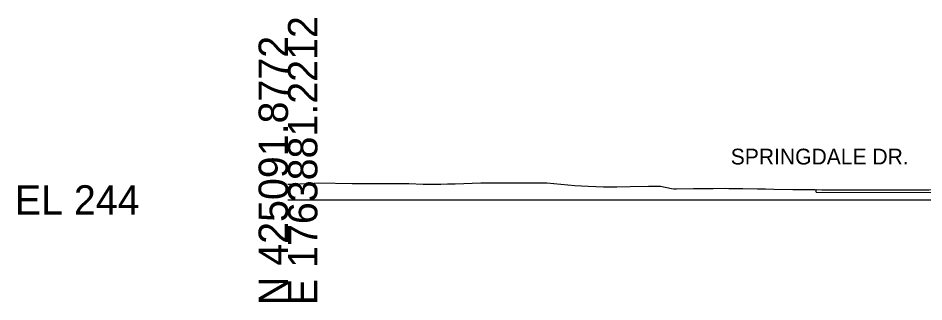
# Model space of a CAD drawing. Extents: x -26 to 3203, y -11010 to 4024.
# Drawn here: x 2974.3 to 3060.5, y -3509.7 to -3482.7 of the extents above; entities that cross this region are included whole.
import ezdxf

# ---------------------------------------------------------------- set-up
doc = ezdxf.new("R2010")
doc.units = 0
for name, color, linetype in [('Default', 7, 'Continuous'), ('Exist Cross Section Cell', 7, 'Continuous'), ('Exist XS Ground Line', 7, 'Continuous'), ('Prop CMT Pvmt Course 1', 7, 'Continuous'), ('Prop CMT Pvmt Surface', 7, 'Continuous'), ('Prop XS SE Text', 7, 'Continuous')]:
    doc.layers.add(name, color=color, linetype=linetype)

msp = doc.modelspace()

# ---------------------------------------------------------------- linework, layer by layer
at = {"layer": 'Exist Cross Section Cell'}
msp.add_line((3000, -3500), (3100, -3500), dxfattribs=at)
at = {"layer": 'Exist XS Ground Line'}
msp.add_lwpolyline([(3000, -3498.495), (3000.176, -3498.49), (3002.071, -3498.448), (3002.899, -3498.368), (3006.114, -3498.432), (3011.519, -3498.419), (3012.857, -3498.501), (3013.88, -3498.488), (3014.564, -3498.482), (3015.184, -3498.478), (3015.901, -3498.477), (3018.345, -3498.38), (3021.749, -3498.375), (3024.64, -3498.385), (3027.295, -3498.618), (3028.566, -3498.685), (3030.035, -3498.741), (3031.303, -3498.753), (3032.586, -3498.733), (3034.312, -3498.7), (3035.466, -3498.697), (3036.499, -3498.897), (3036.734, -3498.94), (3036.856, -3498.937), (3036.971, -3498.936), (3038.612, -3498.907), (3040.426, -3498.906), (3040.469, -3498.906), (3041.674, -3498.892), (3041.971, -3498.896), (3042.355, -3498.902), (3043.294, -3498.925), (3044.688, -3498.937), (3045.454, -3498.951), (3046.244, -3498.964), (3048.057, -3498.992), (3048.956, -3498.998), (3050.175, -3499.014), (3050.829, -3499.022), (3051.326, -3499.03), (3052.495, -3499.028), (3054.206, -3499.03), (3054.392, -3499.03), (3054.534, -3499.03), (3056.287, -3499.035), (3057.682, -3499.038), (3057.921, -3499.039), (3059.657, -3499.032), (3061.03, -3499.051)], dxfattribs=at)
msp.add_lwpolyline([(3000, -3498.495), (3000.176, -3498.49), (3002.071, -3498.448), (3002.899, -3498.368), (3006.114, -3498.432), (3011.519, -3498.419), (3012.857, -3498.501), (3013.88, -3498.488), (3014.564, -3498.482), (3015.184, -3498.478), (3015.901, -3498.477), (3018.345, -3498.38), (3021.749, -3498.375), (3024.64, -3498.385), (3027.295, -3498.618), (3028.566, -3498.685), (3030.035, -3498.741), (3031.303, -3498.753), (3032.586, -3498.733), (3034.312, -3498.7), (3035.466, -3498.697), (3036.499, -3498.897), (3036.734, -3498.94), (3036.856, -3498.937), (3036.971, -3498.936), (3038.612, -3498.907), (3040.426, -3498.906), (3040.469, -3498.906), (3041.674, -3498.892), (3041.971, -3498.896), (3042.355, -3498.902), (3043.294, -3498.925), (3044.688, -3498.937), (3045.454, -3498.951), (3046.244, -3498.964), (3048.057, -3498.992), (3048.956, -3498.998), (3050.175, -3499.014), (3050.829, -3499.022), (3051.326, -3499.03), (3052.495, -3499.028), (3054.206, -3499.03), (3054.392, -3499.03), (3054.534, -3499.03), (3056.287, -3499.035), (3057.682, -3499.038), (3057.921, -3499.039), (3059.657, -3499.032), (3061.03, -3499.051)], dxfattribs=at)
msp.add_lwpolyline([(3000, -3498.495), (3000.176, -3498.49), (3002.071, -3498.448), (3002.899, -3498.368), (3006.114, -3498.432), (3011.519, -3498.419), (3012.857, -3498.501), (3013.88, -3498.488), (3014.564, -3498.482), (3015.184, -3498.478), (3015.901, -3498.477), (3018.345, -3498.38), (3021.749, -3498.375), (3024.64, -3498.385), (3027.295, -3498.618), (3028.566, -3498.685), (3030.035, -3498.741), (3031.303, -3498.753), (3032.586, -3498.733), (3034.312, -3498.7), (3035.466, -3498.697), (3036.499, -3498.897), (3036.734, -3498.94), (3036.856, -3498.937), (3036.971, -3498.936), (3038.612, -3498.907), (3040.426, -3498.906), (3040.469, -3498.906), (3041.674, -3498.892), (3041.971, -3498.896), (3042.355, -3498.902), (3043.294, -3498.925), (3044.688, -3498.937), (3045.454, -3498.951), (3046.244, -3498.964), (3048.057, -3498.992), (3048.956, -3498.998), (3050.175, -3499.014), (3050.829, -3499.022), (3051.326, -3499.03), (3052.495, -3499.028), (3054.206, -3499.03), (3054.392, -3499.03), (3054.534, -3499.03), (3056.287, -3499.035), (3057.682, -3499.038), (3057.921, -3499.039), (3059.657, -3499.032), (3061.03, -3499.051)], dxfattribs=at)
msp.add_lwpolyline([(3000, -3498.495), (3000.176, -3498.49), (3002.071, -3498.448), (3002.899, -3498.368), (3006.114, -3498.432), (3011.519, -3498.419), (3012.857, -3498.501), (3013.88, -3498.488), (3014.564, -3498.482), (3015.184, -3498.478), (3015.901, -3498.477), (3018.345, -3498.38), (3021.749, -3498.375), (3024.64, -3498.385), (3027.295, -3498.618), (3028.566, -3498.685), (3030.035, -3498.741), (3031.303, -3498.753), (3032.586, -3498.733), (3034.312, -3498.7), (3035.466, -3498.697), (3036.499, -3498.897), (3036.734, -3498.94), (3036.856, -3498.937), (3036.971, -3498.936), (3038.612, -3498.907), (3040.426, -3498.906), (3040.469, -3498.906), (3041.674, -3498.892), (3041.971, -3498.896), (3042.355, -3498.902), (3043.294, -3498.925), (3044.688, -3498.937), (3045.454, -3498.951), (3046.244, -3498.964), (3048.057, -3498.992), (3048.956, -3498.998), (3050.175, -3499.014), (3050.829, -3499.022), (3051.326, -3499.03), (3052.495, -3499.028), (3054.206, -3499.03), (3054.392, -3499.03), (3054.534, -3499.03), (3056.287, -3499.035), (3057.682, -3499.038), (3057.921, -3499.039), (3059.657, -3499.032), (3061.03, -3499.051)], dxfattribs=at)
msp.add_lwpolyline([(3000, -3498.495), (3000.176, -3498.49), (3002.071, -3498.448), (3002.899, -3498.368), (3006.114, -3498.432), (3011.519, -3498.419), (3012.857, -3498.501), (3013.88, -3498.488), (3014.564, -3498.482), (3015.184, -3498.478), (3015.901, -3498.477), (3018.345, -3498.38), (3021.749, -3498.375), (3024.64, -3498.385), (3027.295, -3498.618), (3028.566, -3498.685), (3030.035, -3498.741), (3031.303, -3498.753), (3032.586, -3498.733), (3034.312, -3498.7), (3035.466, -3498.697), (3036.499, -3498.897), (3036.734, -3498.94), (3036.856, -3498.937), (3036.971, -3498.936), (3038.612, -3498.907), (3040.426, -3498.906), (3040.469, -3498.906), (3041.674, -3498.892), (3041.971, -3498.896), (3042.355, -3498.902), (3043.294, -3498.925), (3044.688, -3498.937), (3045.454, -3498.951), (3046.244, -3498.964), (3048.057, -3498.992), (3048.956, -3498.998), (3050.175, -3499.014), (3050.829, -3499.022), (3051.326, -3499.03), (3052.495, -3499.028), (3054.206, -3499.03), (3054.392, -3499.03), (3054.534, -3499.03), (3056.287, -3499.035), (3057.682, -3499.038), (3057.921, -3499.039), (3059.657, -3499.032), (3061.03, -3499.051)], dxfattribs=at)
at = {"layer": 'Prop CMT Pvmt Course 1'}
for q in [(3050.271, -3499.015), (3062.323, -3499.302)]:
    msp.add_line((3050.271, -3499.265), q, dxfattribs=at)
at = {"layer": 'Prop CMT Pvmt Surface'}
msp.add_line((3050.271, -3499.015), (3062.323, -3499.052), dxfattribs=at)

# ---------------------------------------------------------------- texts
at = {"layer": 'Default'}
msp.add_text('-', height=0.0001, dxfattribs=at).set_placement((3000, -3500))
at = {"layer": 'Exist Cross Section Cell'}
for s, p in [('E 1763881.2212', (3002.8, -3510)), ('N 425091.8772', (3000, -3510))]:
    msp.add_text(s, height=2.8, rotation=90, dxfattribs=at).set_placement(p)
msp.add_text('EL 244', height=2.8, dxfattribs=at).set_placement((2974, -3501.4))
at = {"layer": 'Prop XS SE Text'}
msp.add_text('SPRINGDALE DR.', height=1.5, rotation=360, dxfattribs=at).set_placement((3042.15, -3496.625))

doc.saveas('drawing.dxf')
